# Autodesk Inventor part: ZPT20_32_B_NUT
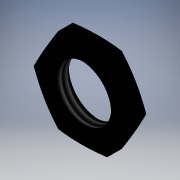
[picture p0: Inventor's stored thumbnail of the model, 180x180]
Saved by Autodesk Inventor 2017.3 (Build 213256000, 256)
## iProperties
Part Number: ZPT20_32_B_NUT
Material: Generic
Catalog Web Link: www.cadenas.de
Description: ZPT_20_32B_NUT-Vacuum Pad/Vertical Vacuum Entry With Buffer
Vendor: SMC
Document SubType Name: Modeling
Designer: partserver
Manufacturer: SMC
Mass: 0.310564 g
Surface Area: 4.18569 cm^2
Volume: 0.310564 cm^3
Density: 1 g/cm^3
Appearance: PSOLRGB-0-0-0
Category: PARTsolutions
Company: SMC
Title: ZPT20_32_B_NUT
Author: Cadenas PARTsolutions
Comments: Vacuum Pad/Vertical Vacuum Entry With Buffer
PSOL_IDENT_0: {$CADENAS_DATA\23d-libs\smc_jp\vacuum_equipment\vacuum_pad\zp\zpt_b\zpt_20_32_b\parts\zpt_20_32_nut_
PSOL_IDENT_1: b.prj},176 {VTYP=3D},{NB=ZPT20_32_B_NUT},{LINA=ZPT20_32_B_NUT},{NN=ZPT_20_32B_NUT},{DATE=03.02.2021
PSOL_IDENT_2: 04:15:19},{GEOMDATE=10.02.2011 07:48:00},{VERSION=},{LINEID=10},{WBVAR=},{WBNUMERIC=}  {NB=ZPT20_32_
PSOL_IDENT_3: B_NUT},{LINA=ZPT20_32_B_NUT},{KT=DUMMY},{ORDER=ZPT20_32}
NB: ZPT20_32_B_NUT
NN: ZPT_20_32B_NUT
NT: Vacuum Pad/Vertical Vacuum Entry With Buffer
NBSYN: $ORDER._B_NUT
LINA: ZPT20_32_B_NUT
CATALOG: SMC (JP
ORDER: ZPT20_32
SUPPLIER: SMC
ARTICLENO: ZPT20_32_B_NUT
BOMINFO: ZPT20_32_B_NUT
CREATOR: CADENAS GmbH
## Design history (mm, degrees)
sketch "Sketch_1"
  geometry: L1 (0, -1.5)-(0, 1.5); L2 (4.458, 0.959)-(4.458, -0.959); L3 (4.458, -0.959)-(5, -1.5); L4 (5, -1.5)-(7, -1.5); L5 (7, -1.5)-(9.6, -0.803); L6 (9.6, -0.803)-(9.6, 0.803); L7 (9.6, 0.803)-(7, 1.5); L8 (7, 1.5)-(5, 1.5); L9 (5, 1.5)-(4.458, 0.959)
  constraints: 18 end point
revolve "Revolution1" sketch "Sketch_1" stored, may be unused: angle "d0" = 360 deg
thread "Thread1" dims "d1" = 1.917, "d2" = 0
sketch "Sketch_2"
  geometry: L1 (8.083, 0)-(4.041, 7); L2 (4.041, 7)-(-4.041, 7); L3 (-4.041, 7)-(-8.083, 0); L4 (-8.083, 0)-(-4.041, -7); L5 (-4.041, -7)-(4.041, -7); L6 (4.041, -7)-(8.083, 0); C1 r 12 at (0, 0); 1 further point
  constraints: 12 end point, 1 centre point
extrude "Extrusion1" cut sketch "Sketch_2" stored distance "d3" = 3; taper "d4" = 0 deg
node "NUT_BUFFER_XY"
node "NUT_BUFFER_YZ"
node "NUT_BUFFER_ZX"
node "NUT_BUFFER_X"
node "NUT_BUFFER_Y"
node "NUT_BUFFER_Z"
node "NUT_BUFFER_Center"
body "Solid1"
